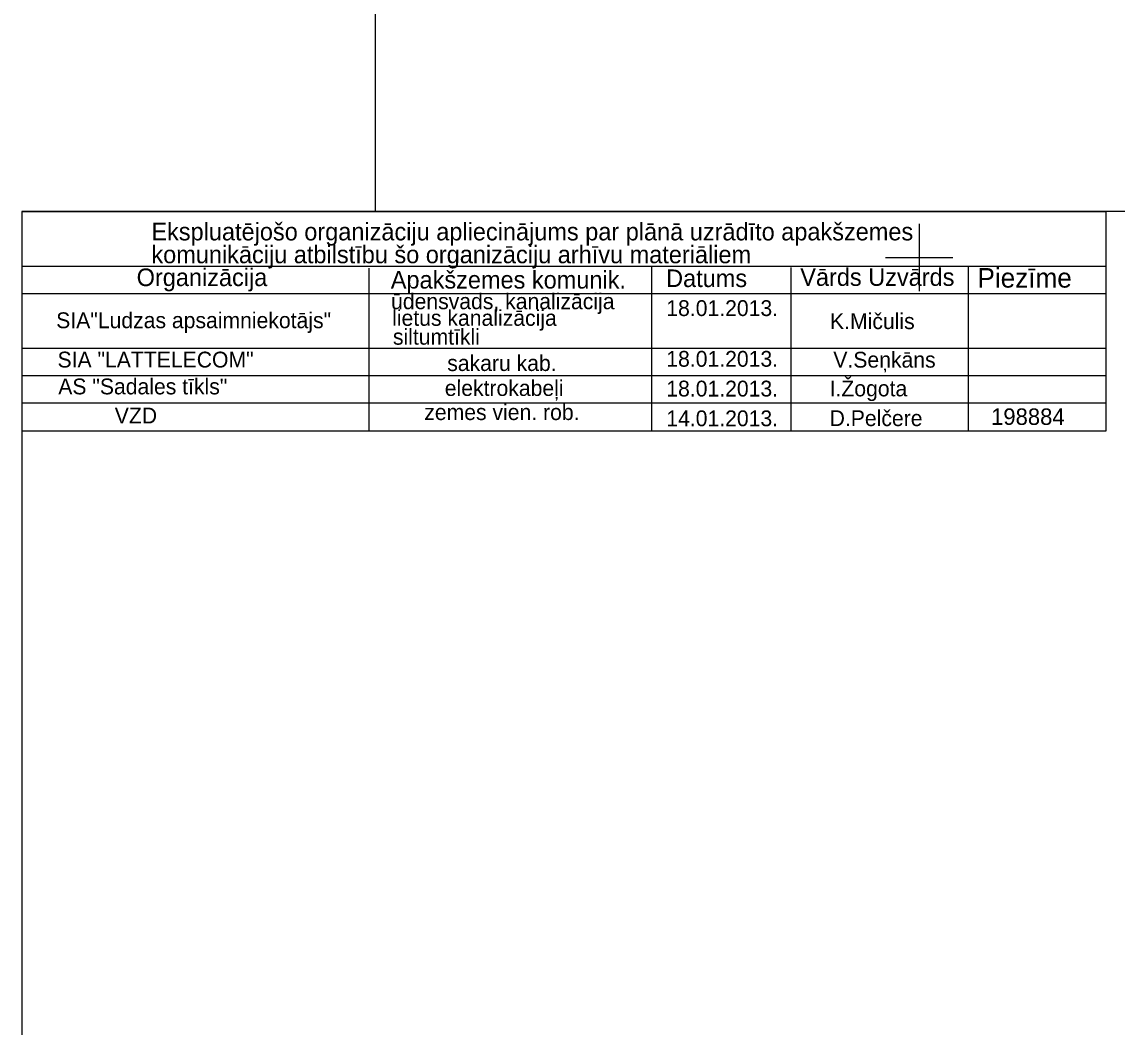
# Model space of a CAD drawing. Extents: x 728710 to 728960, y 272811 to 273475.
# Drawn here: x 728709.9 to 728768.6, y 273158.4 to 273212.2 of the extents above; entities that cross this region are included whole.
import ezdxf

# ---------------------------------------------------------------- set-up
doc = ezdxf.new("R2010")
doc.units = 0
doc.layers.add('Level 10', color=7, linetype='Continuous')
doc.layers.add('RAMI_PLAN_####_TKST_#', color=7, linetype='Continuous')

msp = doc.modelspace()

# ---------------------------------------------------------------- linework, layer by layer
at = {"layer": 'Level 10'}
for p, q in [((728758.012, 273201.39), (728758.012, 273199.59)), ((728756.212, 273199.59), (728758.012, 273199.59)), ((728758.012, 273199.59), (728758.012, 273197.79)), ((728758.012, 273199.59), (728759.812, 273199.59))]:
    msp.add_line(p, q, dxfattribs=at)
at = {"layer": 'RAMI_PLAN_####_TKST_#'}
for p, q in [((728709.939, 273202.048), (728768.031, 273202.048)), ((728709.939, 273199.117), (728768.031, 273199.116)), ((728728.535, 273190.291), (728728.535, 273199.006)), ((728743.681, 273190.291), (728743.681, 273199.117)), ((728751.155, 273190.291), (728751.155, 273199.043)), ((728760.646, 273190.291), (728760.646, 273199.08)), ((728709.939, 273197.655), (728768.031, 273197.655)), ((728709.939, 273194.732), (728768.031, 273194.731)), ((728709.939, 273193.27), (728768.031, 273193.27)), ((728709.939, 273191.808), (728768.031, 273191.808)), ((728709.939, 273190.291), (728768.031, 273190.291))]:
    msp.add_line(p, q, dxfattribs=at)
for points in [[(728728.89, 273202.048), (728728.89, 273475.126), (728912.915, 273475.126), (728912.915, 273202.048)], [(728709.938, 272811.037), (728959.516, 272811.036), (728959.516, 273202.048), (728709.939, 273202.048)]]:
    msp.add_lwpolyline(points, close=True, dxfattribs=at)
for points in [[(728709.939, 273202.048), (728709.939, 273186.998)], [(728768.031, 273190.291), (728768.031, 273202.048)]]:
    msp.add_lwpolyline(points, dxfattribs=at)

# ---------------------------------------------------------------- texts
for s, height, rotation, p in [(' Ekspluatējošo organizāciju apliecinājums par plānā uzrādīto apakšzemes', 0.94182, 359.99995, (728716.526, 273200.502)), (' komunikāciju atbilstību šo organizāciju arhīvu materiāliem', 0.94182, 359.99995, (728716.526, 273199.278)), ('Organizācija', 0.94182, 359.99995, (728716.086, 273198.054)), ('Apakšzemes komunik.', 0.94182, 359.99995, (728729.702, 273197.922)), ('Datums', 0.9418, 359.99995, (728744.451, 273198.002)), ('Vārds Uzvārds', 0.94182, 359.99995, (728751.639, 273198.066)), ('Piezīme', 1.0465, 359.99995, (728761.132, 273197.972)), ('ūdensvads, kanalizācija', 0.84764, 359.99987, (728729.716, 273196.817)), ('lietus kanalizācija', 0.84764, 359.99974, (728729.774, 273195.925)), ('18.01.2013.', 0.84764, 359.99995, (728744.462, 273196.45)), ('SIA"Ludzas apsaimniekotājs"', 0.84764, 359.99974, (728711.775, 273195.799)), ('K.Mičulis', 0.8476, 359.99974, (728753.234, 273195.75)), ('siltumtīkli', 0.84764, 359.99974, (728729.816, 273194.915)), ('SIA "LATTELECOM"', 0.84764, 359.99974, (728711.847, 273193.693)), ('18.01.2013.', 0.84764, 359.99995, (728744.462, 273193.733)), ('V.Seņkāns', 0.8476, 359.99974, (728753.41, 273193.686)), ('sakaru kab.', 0.84764, 359.99995, (728732.726, 273193.505)), ('AS "Sadales tīkls"', 0.84764, 359.99974, (728711.886, 273192.253)), ('elektrokabeļi', 0.84764, 359.99974, (728732.594, 273192.169)), ('18.01.2013.', 0.84764, 359.99995, (728744.462, 273192.139)), ('I.Žogota', 0.8476, 359.99974, (728753.212, 273192.147)), ('VZD', 0.8476, 359.99974, (728714.913, 273190.693)), ('zemes vien. rob.', 0.84764, 359.99974, (728731.496, 273190.877)), ('14.01.2013.', 0.84764, 359.99995, (728744.462, 273190.546)), ('D.Pelčere', 0.8476, 359.99974, (728753.212, 273190.554))]:
    msp.add_text(s, height=height, rotation=rotation, dxfattribs=at).set_placement(p)
msp.add_text('198884', height=0.883, dxfattribs=at).set_placement((728761.862, 273190.617))

doc.saveas('drawing.dxf')
